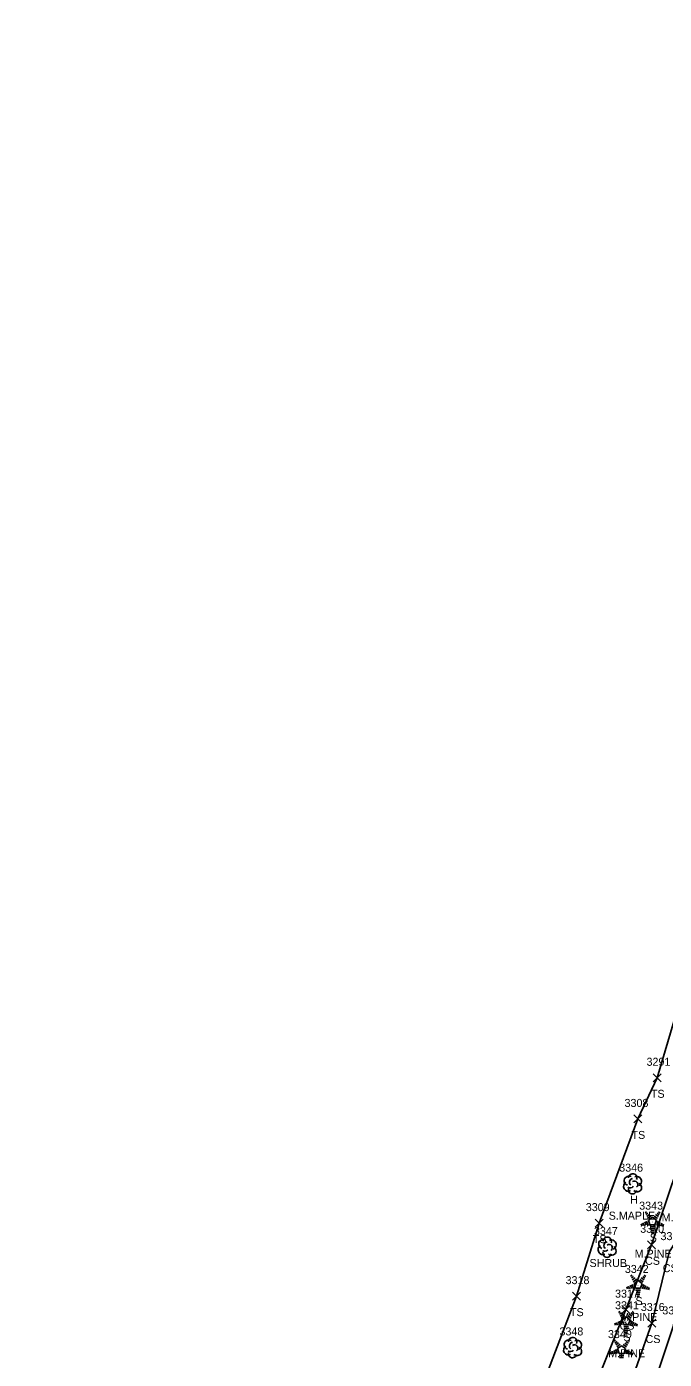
# Model space of a CAD drawing. Extents: x 1462089 to 1464015, y 730534 to 736144.
# Drawn here: x 1462771.8 to 1462931.1, y 732694.9 to 733027.8 of the extents above; entities that cross this region are included whole.
import ezdxf

# ---------------------------------------------------------------- set-up
doc = ezdxf.new("R2010")
doc.units = 0
for name, color, linetype in [('L_A', 7, 'Continuous'), ('L_C', 7, 'Continuous'), ('L_I', 7, 'Continuous'), ('L_TIC', 7, 'Continuous'), ('LARO', 7, 'Continuous'), ('LELB', 7, 'Continuous'), ('LSH', 7, 'Continuous'), ('LTC', 7, 'Continuous'), ('LTD', 7, 'Continuous')]:
    doc.layers.add(name, color=color, linetype=linetype)

msp = doc.modelspace()

# ---------------------------------------------------------------- linework, layer by layer
at = {"layer": 'L_TIC'}
for points in [[(1462928.37, 732764.22), (1462930.37, 732766.22)], [(1462930.37, 732764.22), (1462928.37, 732766.22)], [(1462928.37, 732764.22), (1462930.37, 732766.22)], [(1462930.37, 732764.22), (1462928.37, 732766.22)], [(1462923.52, 732753.94), (1462925.52, 732755.94)], [(1462925.52, 732753.94), (1462923.52, 732755.94)], [(1462913.85, 732727.91), (1462915.85, 732729.91)], [(1462915.85, 732727.91), (1462913.85, 732729.91)], [(1462926.88, 732722.49), (1462928.88, 732724.49)], [(1462928.88, 732722.49), (1462926.88, 732724.49)], [(1462908.15, 732709.66), (1462910.15, 732711.66)], [(1462910.15, 732709.66), (1462908.15, 732711.66)], [(1462920.5, 732706.29), (1462922.5, 732708.29)], [(1462922.5, 732706.29), (1462920.5, 732708.29)], [(1462926.99, 732702.95), (1462928.99, 732704.95)], [(1462928.99, 732702.95), (1462926.99, 732704.95)]]:
    msp.add_lwpolyline(points, dxfattribs=at)
at = {"layer": 'LARO'}
msp.add_lwpolyline([(1462963.59, 732800.47), (1462962.77, 732786.08), (1462955.81, 732768.23), (1462949.84, 732750.15), (1462943.9, 732732.26), (1462937.19, 732721.71), (1462933.31, 732703.1), (1462919.19, 732660.62), (1462912.54, 732624.66), (1462906.91, 732612.5), (1462913.19, 732613.5)], dxfattribs=at)
at = {"layer": 'LELB'}
for points in [[(1463024.96, 733052.89), (1463019.37, 733009.96), (1463000.01, 732962.33), (1462984.86, 732926.01), (1462972.76, 732908.94), (1462960.37, 732884.47), (1462958.09, 732841.86), (1462948.33, 732829.18), (1462951.8, 732798.65), (1462940.09, 732777.68), (1462936.2, 732747.89), (1462927.88, 732723.49), (1462921.5, 732707.29), (1462904.86, 732665.94), (1462895.56, 732628.88), (1462895.22, 732616.02)], [(1463021.17, 732953.09), (1462994.97, 732923.37), (1462984.02, 732905.02), (1462972.48, 732877.45), (1462971.14, 732833.65), (1462963.59, 732800.47), (1462958.53, 732787.78), (1462952.68, 732768.33), (1462946.4, 732751.12), (1462940.6, 732734.98), (1462932.3, 732721.66), (1462927.99, 732703.95), (1462913.72, 732663.31)], [(1462929.37, 732765.22), (1462940.63, 732803.46), (1462938.45, 732816.71), (1462939.43, 732831.35)], [(1462929.37, 732765.22), (1462924.52, 732754.94), (1462914.85, 732728.91), (1462909.15, 732710.66), (1462894.31, 732671.59), (1462879.19, 732633.1), (1462871.41, 732624.99), (1462862.28, 732600.59), (1462856.74, 732586.46), (1462855.85, 732579.52), (1462844.58, 732549.89), (1462835, 732527.85), (1462823.24, 732513.34), (1462809.83, 732498.46), (1462790.98, 732495.54), (1462771.85, 732493.04)]]:
    msp.add_lwpolyline(points, dxfattribs=at)
at = {"layer": 'LSH'}
msp.add_line((1462916.81, 732722.94), (1462916.81, 732722.94), dxfattribs=at)
msp.add_line((1462916.81, 732722.94), (1462916.81, 732722.94), dxfattribs=at)
msp.add_arc((1462916.85, 732724.38), 1.05, 335.5272, 180.9563, dxfattribs=at)
for centre, major_axis, ratio, start_param, end_param in [((1462916.01, 732723.61), (1.21, -0.51), 0.895232, 1.570796, 4.712389), ((1462916.6, 732723.4), (-0.208, -0.792), 0.645439, 3.141593, 6.283185), ((1462917.31, 732722.77), (-0.5, 0.667), 0.989748, 3.141593, 6.283185), ((1462917.85, 732723.52), (-1.14, -0.48), 0.949671, 1.570796, 4.712389), ((1462915.72, 732722.23), (0.58, -1.04), 0.959034, 3.141593, 6.283185), ((1462916.81, 732721.44), (0.26, 1.06), 0.942809, 1.570796, 4.712389), ((1462916.35, 732722.19), (-0.625, -0.083), 0.423636, 0, 3.141593), ((1462917.81, 732722.11), (-1.09, 0.79), 0.841452, 1.570796, 4.712389)]:
    msp.add_ellipse(centre, major_axis=major_axis, ratio=ratio, start_param=start_param, end_param=end_param, dxfattribs=at)
at = {"layer": 'LTC'}
for p, q in [((1462926.3, 732731.48), (1462926.65, 732731.74)), ((1462926.51, 732731.02), (1462927.04, 732731.4)), ((1462926.72, 732730.55), (1462927.42, 732731.06)), ((1462926.93, 732730.09), (1462927.8, 732730.73)), ((1462927.15, 732729.63), (1462928.16, 732730.37)), ((1462928.16, 732730.37), (1462929.16, 732729.64)), ((1462928.58, 732730.68), (1462929.39, 732730.09)), ((1462928.95, 732731.03), (1462929.63, 732730.53)), ((1462929.32, 732731.38), (1462929.87, 732730.98)), ((1462929.7, 732731.72), (1462930.12, 732731.42)), ((1462925.33, 732728.76), (1462925.48, 732728.3)), ((1462925.79, 732728.98), (1462926, 732728.33)), ((1462926.24, 732729.2), (1462926.51, 732728.36)), ((1462926.7, 732729.41), (1462927.03, 732728.39)), ((1462927.15, 732729.63), (1462927.54, 732728.44)), ((1462928.77, 732728.44), (1462927.54, 732728.44)), ((1462928.73, 732727.94), (1462927.59, 732727.94)), ((1462928.65, 732727.44), (1462927.66, 732727.44)), ((1462928.56, 732726.94), (1462927.73, 732726.94)), ((1462929.16, 732729.64), (1462928.77, 732728.44)), ((1462929.6, 732729.37), (1462929.26, 732728.33)), ((1462930.04, 732729.12), (1462929.75, 732728.24)), ((1462930.49, 732728.87), (1462930.25, 732728.14)), ((1462930.93, 732728.62), (1462930.74, 732728.05)), ((1462928.48, 732726.44), (1462927.8, 732726.44)), ((1462922.71, 732715.67), (1462923.07, 732715.93)), ((1462922.92, 732715.2), (1462923.45, 732715.59)), ((1462923.11, 732713.6), (1462923.44, 732712.58)), ((1462923.13, 732714.74), (1462923.84, 732715.25)), ((1462923.34, 732714.27), (1462924.22, 732714.91)), ((1462923.57, 732713.82), (1462924.58, 732714.55)), ((1462923.57, 732713.82), (1462923.95, 732712.62)), ((1462924.58, 732714.55), (1462925.58, 732713.83)), ((1462925, 732714.86), (1462925.81, 732714.27)), ((1462925.58, 732713.83), (1462925.19, 732712.62)), ((1462925.37, 732715.21), (1462926.05, 732714.72)), ((1462926.01, 732713.55), (1462925.68, 732712.51)), ((1462925.74, 732715.56), (1462926.29, 732715.16)), ((1462926.11, 732715.91), (1462926.53, 732715.6)), ((1462921.75, 732712.95), (1462921.9, 732712.48)), ((1462922.2, 732713.16), (1462922.41, 732712.51)), ((1462922.66, 732713.38), (1462922.93, 732712.54)), ((1462925.19, 732712.62), (1462923.95, 732712.62)), ((1462925.15, 732712.12), (1462924, 732712.12)), ((1462925.06, 732711.62), (1462924.07, 732711.62)), ((1462924.98, 732711.12), (1462924.15, 732711.12)), ((1462924.9, 732710.62), (1462924.22, 732710.62)), ((1462926.46, 732713.3), (1462926.17, 732712.42)), ((1462926.9, 732713.05), (1462926.67, 732712.32)), ((1462927.35, 732712.8), (1462927.16, 732712.23)), ((1462919.71, 732706.59), (1462920.07, 732706.85)), ((1462923.11, 732706.83), (1462923.53, 732706.53)), ((1462918.75, 732703.87), (1462918.9, 732703.4)), ((1462919.2, 732704.09), (1462919.41, 732703.44)), ((1462919.66, 732704.31), (1462919.93, 732703.47)), ((1462919.92, 732706.13), (1462920.45, 732706.51)), ((1462920.11, 732704.52), (1462920.44, 732703.5)), ((1462920.13, 732705.66), (1462920.84, 732706.17)), ((1462920.34, 732705.2), (1462921.22, 732705.83)), ((1462920.57, 732704.74), (1462921.58, 732705.48)), ((1462920.57, 732704.74), (1462920.95, 732703.55)), ((1462922.18, 732703.55), (1462920.95, 732703.55)), ((1462921.58, 732705.48), (1462922.57, 732704.75)), ((1462922, 732705.79), (1462922.81, 732705.2)), ((1462922.57, 732704.75), (1462922.18, 732703.55)), ((1462922.37, 732706.14), (1462923.05, 732705.64)), ((1462923.01, 732704.48), (1462922.67, 732703.44)), ((1462922.74, 732706.49), (1462923.29, 732706.09)), ((1462923.46, 732704.23), (1462923.17, 732703.34)), ((1462923.9, 732703.98), (1462923.66, 732703.25)), ((1462924.35, 732703.73), (1462924.16, 732703.15)), ((1462922.15, 732703.05), (1462921, 732703.05)), ((1462922.06, 732702.55), (1462921.07, 732702.55)), ((1462921.98, 732702.05), (1462921.15, 732702.05)), ((1462921.89, 732701.55), (1462921.22, 732701.55)), ((1462918.07, 732696.89), (1462918.29, 732696.24)), ((1462918.53, 732697.11), (1462918.8, 732696.27)), ((1462918.59, 732699.39), (1462918.94, 732699.65)), ((1462918.8, 732698.93), (1462919.33, 732699.31)), ((1462918.99, 732697.32), (1462919.32, 732696.3)), ((1462919.01, 732698.46), (1462919.71, 732698.97)), ((1462919.22, 732698), (1462920.09, 732698.63)), ((1462919.44, 732697.54), (1462920.45, 732698.28)), ((1462919.44, 732697.54), (1462919.83, 732696.35)), ((1462920.45, 732698.28), (1462921.45, 732697.55)), ((1462920.87, 732698.59), (1462921.68, 732698)), ((1462921.45, 732697.55), (1462921.06, 732696.35)), ((1462921.24, 732698.94), (1462921.92, 732698.44)), ((1462921.89, 732697.28), (1462921.55, 732696.24)), ((1462921.61, 732699.28), (1462922.16, 732698.89)), ((1462921.99, 732699.63), (1462922.4, 732699.33)), ((1462922.33, 732697.03), (1462922.04, 732696.14)), ((1462917.62, 732696.67), (1462917.77, 732696.2)), ((1462921.06, 732696.35), (1462919.83, 732696.35)), ((1462921.02, 732695.85), (1462919.87, 732695.85)), ((1462920.94, 732695.35), (1462919.95, 732695.35)), ((1462922.78, 732696.78), (1462922.54, 732696.05)), ((1462923.22, 732696.53), (1462923.03, 732695.95))]:
    msp.add_line(p, q, dxfattribs=at)
at = {"layer": 'LTD'}
for p, q in [((1462923.17, 732738.77), (1462923.17, 732738.77)), ((1462923.17, 732738.77), (1462923.17, 732738.77)), ((1462908.19, 732697.85), (1462908.19, 732697.85)), ((1462908.19, 732697.85), (1462908.19, 732697.85))]:
    msp.add_line(p, q, dxfattribs=at)
for centre in [(1462923.22, 732740.2), (1462908.23, 732699.29)]:
    msp.add_arc(centre, 1.05, 335.5272, 180.9563, dxfattribs=at)
for centre, major_axis, ratio, start_param, end_param in [((1462922.38, 732739.44), (1.21, -0.51), 0.895232, 1.570796, 4.712389), ((1462924.21, 732739.35), (-1.14, -0.48), 0.949671, 1.570796, 4.712389), ((1462922.09, 732738.06), (0.58, -1.04), 0.959034, 3.141593, 6.283185), ((1462923.17, 732737.27), (0.26, 1.06), 0.942809, 1.570796, 4.712389), ((1462922.71, 732738.02), (-0.625, -0.083), 0.423636, 0, 3.141593), ((1462922.96, 732739.23), (-0.208, -0.792), 0.645439, 3.141593, 6.283185), ((1462923.67, 732738.6), (-0.5, 0.667), 0.989748, 3.141593, 6.283185), ((1462924.17, 732737.94), (-1.09, 0.79), 0.841452, 1.570796, 4.712389), ((1462907.1, 732697.14), (0.58, -1.04), 0.959034, 3.141593, 6.283185), ((1462907.39, 732698.52), (1.21, -0.51), 0.895232, 1.570796, 4.712389), ((1462907.73, 732697.1), (-0.625, -0.083), 0.423636, 0, 3.141593), ((1462907.98, 732698.31), (-0.208, -0.792), 0.645439, 3.141593, 6.283185), ((1462908.69, 732697.68), (-0.5, 0.667), 0.989748, 3.141593, 6.283185), ((1462909.19, 732697.02), (-1.09, 0.79), 0.841452, 1.570796, 4.712389), ((1462909.23, 732698.44), (-1.14, -0.48), 0.949671, 1.570796, 4.712389), ((1462908.19, 732696.35), (0.26, 1.06), 0.942809, 1.570796, 4.712389)]:
    msp.add_ellipse(centre, major_axis=major_axis, ratio=ratio, start_param=start_param, end_param=end_param, dxfattribs=at)

# ---------------------------------------------------------------- texts
at = {"layer": 'L_A'}
for s, p in [('TS', (1462927.78, 732760.22)), ('TS', (1462927.78, 732760.22)), ('TS', (1462922.93, 732749.94)), ('H', (1462922.6, 732733.77)), ('TS', (1462913.26, 732723.91)), ('S', (1462927.49, 732724.28)), ('CS', (1462926.32, 732718.49)), ('SHRUB', (1462912.44, 732717.94)), ('CS', (1462930.74, 732716.66)), ('S', (1462923.9, 732708.46)), ('TS', (1462907.56, 732705.66)), ('CS', (1462919.94, 732702.29)), ('S', (1462920.9, 732699.39)), ('CS', (1462926.44, 732698.95))]:
    msp.add_text(s, height=2, dxfattribs=at).set_placement(p)
at = {"layer": 'L_C'}
for s, p in [('S.MAPLE', (1462917.23, 732729.77)), ('M.PINE', (1462930.46, 732729.35)), ('M.PINE', (1462923.71, 732720.28)), ('M.PINE', (1462920.13, 732704.46)), ('M.PINE', (1462917.12, 732695.39))]:
    msp.add_text(s, height=2, dxfattribs=at).set_placement(p)
at = {"layer": 'L_I'}
for s, p in [('3291', (1462926.68, 732768.22)), ('3291', (1462926.68, 732768.22)), ('3308', (1462921.19, 732757.94)), ('3346', (1462919.86, 732741.77)), ('3309', (1462911.51, 732731.91)), ('3343', (1462924.84, 732732.28)), ('3347', (1462913.55, 732725.94)), ('3310', (1462925.1, 732726.49)), ('3311', (1462930.17, 732724.66)), ('3342', (1462921.26, 732716.46)), ('3318', (1462906.46, 732713.66)), ('3317', (1462918.81, 732710.29)), ('3341', (1462918.82, 732707.39)), ('3316', (1462925.25, 732706.95)), ('3315', (1462930.62, 732706.1)), ('3348', (1462904.93, 732700.85)), ('3340', (1462917.05, 732700.18))]:
    msp.add_text(s, height=2, dxfattribs=at).set_placement(p)
at = {"layer": 'LTC'}
for p in [(1462928.05, 732729.38), (1462924.46, 732713.56), (1462921.46, 732704.49), (1462920.33, 732697.29)]:
    msp.add_text('.', height=1.04, rotation=270, dxfattribs=at).set_placement(p)

doc.saveas('drawing.dxf')
